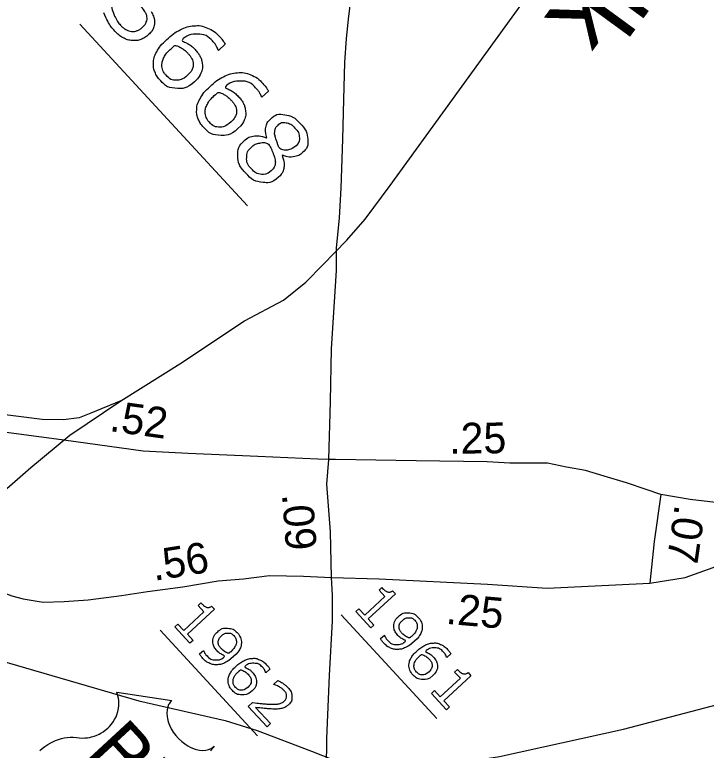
# Model space of a CAD drawing. Extents: x 1695041 to 1706254, y 786537 to 798223.
# Drawn here: x 1703301.4 to 1703431.2, y 796996.4 to 797134.4 of the extents above; entities that cross this region are included whole.
import ezdxf

# ---------------------------------------------------------------- set-up
doc = ezdxf.new("R2010")
doc.units = 0
for name, color, linetype in [('Default', 7, 'Continuous'), ('Old_Level_13', 7, 'Continuous'), ('Old_Level_29', 7, 'Continuous'), ('Old_Level_32', 7, 'Continuous'), ('Sheet Title CELL', 7, 'Continuous')]:
    doc.layers.add(name, color=color, linetype=linetype)

msp = doc.modelspace()

# ---------------------------------------------------------------- linework, layer by layer
at = {"layer": 'Default'}
for p, q in [((1703313.64, 797132.62), (1703345.11, 797098.53)), ((1703362.66, 797021.81), (1703380.63, 797002.34)), ((1703328.71, 797018.93), (1703346.97, 796999.14))]:
    msp.add_line(p, q, dxfattribs=at)
for points in [[(1703340.91, 797128.86), (1703339.66, 797127.7), (1703339.6, 797127.77)], [(1703349.03, 797120.06), (1703347.78, 797118.9), (1703347.72, 797118.97)], [(1703348.68, 797111.29), (1703348.72, 797111.33)], [(1703351.65, 797108.05), (1703351.61, 797108.01)], [(1703321.31, 797061.94), (1703315.69, 797059.63), (1703313.49, 797058.77), (1703310.57, 797058.37), (1703306.6, 797058.49), (1703295.15, 797059.93), (1703289.13, 797061.46), (1703284.84, 797063.34), (1703281.91, 797064.92), (1703278.04, 797067.22)], [(1703368.26, 797019.36), (1703365.44, 797022.42), (1703366.01, 797022.95), (1703367.1, 797021.78), (1703370.89, 797025.27), (1703369.8, 797026.45), (1703370.32, 797026.92)], [(1703372.32, 797026.34), (1703372.86, 797025.75), (1703367.77, 797021.05), (1703368.84, 797019.9), (1703368.26, 797019.36)], [(1703334.31, 797016.48), (1703331.49, 797019.54), (1703332.06, 797020.07), (1703333.15, 797018.9), (1703336.93, 797022.39), (1703335.85, 797023.57), (1703336.37, 797024.04)], [(1703338.37, 797023.46), (1703338.91, 797022.87), (1703333.82, 797018.17), (1703334.89, 797017.02), (1703334.31, 797016.48)], [(1703370.07, 797017.36), (1703370.8, 797018.03), (1703370.83, 797017.99)], [(1703291.97, 797015.19), (1703324.69, 797005.69), (1703340.9, 797002.01), (1703346.94, 797000.11), (1703357.14, 796996.22), (1703368.85, 796991.59), (1703392.4, 796995.22), (1703415.7, 797000.36), (1703437.39, 797006.05), (1703475.08, 797015.18), (1703510.21, 797012.82), (1703534.98, 797011.35), (1703569.35, 797009.42), (1703597.22, 797007.38), (1703614.23, 797006.26), (1703657.83, 797003.31), (1703684.12, 797001.47)], [(1703336.12, 797014.48), (1703336.85, 797015.15), (1703336.88, 797015.11)], [(1703383.24, 797014.5), (1703382.52, 797013.83), (1703382.48, 797013.87)], [(1703349.29, 797011.62), (1703348.57, 797010.95), (1703348.53, 797010.99)], [(1703382.43, 797004.01), (1703379.61, 797007.07), (1703380.19, 797007.6), (1703381.27, 797006.42), (1703385.06, 797009.92), (1703383.97, 797011.09), (1703384.49, 797011.57)], [(1703386.49, 797010.98), (1703387.04, 797010.39), (1703381.95, 797005.69), (1703383.01, 797004.54), (1703382.43, 797004.01)], [(1703350.03, 797008.72), (1703350, 797008.76), (1703350.79, 797009.49)], [(1703306.15, 796996.37), (1703306.57, 796996.73), (1703307.08, 796997.12), (1703307.66, 796997.5), (1703308.17, 796997.8), (1703308.56, 796998), (1703309.06, 796998.22), (1703309.63, 796998.43), (1703310.21, 796998.6), (1703310.71, 796998.72), (1703311.29, 796998.81), (1703311.8, 796998.85), (1703312.42, 796998.85), (1703313.02, 796998.81), (1703313.53, 796998.74), (1703314.19, 796998.71), (1703314.56, 796998.72), (1703315.05, 796998.76), (1703315.48, 796998.83), (1703315.84, 796998.92), (1703316.36, 796999.06), (1703316.73, 796999.19), (1703317.26, 796999.42), (1703317.61, 796999.62), (1703318.04, 796999.88), (1703318.42, 797000.16), (1703318.87, 797000.53), (1703319.21, 797000.87), (1703319.59, 797001.3), (1703319.91, 797001.75), (1703320.17, 797002.16), (1703320.43, 797002.68), (1703320.6, 797003.08), (1703320.78, 797003.68), (1703320.91, 797004.27), (1703320.96, 797004.81), (1703320.98, 797005.32), (1703320.94, 797005.76), (1703320.89, 797006.16), (1703320.8, 797006.64), (1703320.67, 797007.06), (1703320.57, 797007.32), (1703330.9, 797005.73), (1703330.66, 797005.48), (1703330.42, 797005.15), (1703330.31, 797004.97), (1703330.15, 797004.56), (1703330.02, 797004.01), (1703329.97, 797003.39), (1703330.01, 797002.76), (1703330.08, 797002.37), (1703330.23, 797001.76), (1703330.47, 797001.11), (1703330.8, 797000.46), (1703331.18, 796999.83), (1703331.65, 796999.2), (1703332.16, 796998.61), (1703332.78, 796998.04), (1703333.54, 796997.48), (1703333.91, 796997.24), (1703334.35, 796997), (1703334.79, 796996.8), (1703335.31, 796996.62), (1703335.76, 796996.5), (1703336.13, 796996.43), (1703336.73, 796996.39), (1703337.28, 796996.43), (1703337.56, 796996.48), (1703337.81, 796996.55), (1703338.29, 796996.76), (1703338.48, 796996.87), (1703338.84, 796997.15), (1703338.58, 796996.87), (1703338.43, 796996.68), (1703338.3, 796996.48), (1703338.19, 796996.24)], [(1703348.78, 797000.8), (1703345.25, 797004.63), (1703346.05, 797005.37)], [(1703346.63, 797004.45), (1703349.44, 797001.41), (1703348.78, 797000.8)]]:
    msp.add_lwpolyline(points, dxfattribs=at)
for points in [[(1703319.61, 797135.93), (1703319.76, 797135.04), (1703320.21, 797134.07), (1703320.66, 797133.1), (1703321.3, 797132.4), (1703321.68, 797131.99), (1703322.25, 797131.65), (1703322.81, 797131.31), (1703323.35, 797131.27), (1703323.91, 797131.24), (1703324.39, 797131.41), (1703324.88, 797131.58), (1703325.41, 797132.07), (1703325.93, 797132.56), (1703326.12, 797133.04), (1703326.31, 797133.52), (1703326.23, 797134), (1703326.16, 797134.48), (1703325.85, 797134.97), (1703325.54, 797135.45), (1703325.1, 797135.94)], [(1703327.67, 797133.04), (1703327.68, 797132.47), (1703327.44, 797131.87), (1703327.2, 797131.28), (1703326.53, 797130.66), (1703325.86, 797130.04), (1703325.09, 797129.77), (1703324.31, 797129.5), (1703323.49, 797129.56), (1703322.59, 797129.63), (1703321.76, 797130.09), (1703320.93, 797130.55), (1703320.2, 797131.34), (1703319.45, 797132.14), (1703318.92, 797133.1), (1703318.39, 797134.06), (1703318.16, 797134.78)], [(1703327.01, 797135.03), (1703327.24, 797134.66), (1703327.45, 797134.11), (1703327.66, 797133.55), (1703327.67, 797133.04)], [(1703335.18, 797121.83), (1703333.7, 797120.46), (1703331.87, 797120.57), (1703330.03, 797120.68), (1703328.73, 797122.1), (1703328.07, 797122.81), (1703327.75, 797123.6), (1703327.43, 797124.4), (1703327.45, 797125.25), (1703327.47, 797126.31), (1703328.09, 797127.44), (1703328.7, 797128.57), (1703329.96, 797129.73), (1703331.25, 797130.92), (1703332.5, 797131.56), (1703333.76, 797132.21), (1703335.09, 797132.32), (1703336.36, 797132.42), (1703337.61, 797131.9), (1703338.86, 797131.38), (1703339.98, 797130.17), (1703340.33, 797129.78), (1703340.54, 797129.49), (1703340.75, 797129.2), (1703340.91, 797128.86)], [(1703339.6, 797127.77), (1703339.53, 797128.04), (1703339.28, 797128.49), (1703339.03, 797128.94), (1703338.67, 797129.32), (1703337.38, 797130.72), (1703335.73, 797130.75), (1703334.09, 797130.77), (1703332.47, 797129.53), (1703333.31, 797129.29), (1703333.97, 797128.92), (1703334.63, 797128.55), (1703335.27, 797127.85), (1703335.84, 797127.23), (1703336.17, 797126.66), (1703336.49, 797126.08), (1703336.6, 797125.27), (1703336.73, 797124.33), (1703336.39, 797123.48), (1703336.05, 797122.63), (1703335.18, 797121.83)], [(1703333.91, 797123.1), (1703334.51, 797123.66), (1703334.74, 797124.2), (1703334.98, 797124.75), (1703334.89, 797125.43), (1703334.82, 797125.92), (1703334.55, 797126.34), (1703334.28, 797126.77), (1703333.91, 797127.16), (1703333.4, 797127.72), (1703332.83, 797128.07), (1703332.26, 797128.43), (1703331.53, 797128.68), (1703331.37, 797128.56), (1703331.23, 797128.44), (1703331.09, 797128.32), (1703330.89, 797128.14), (1703329.86, 797127.19), (1703329.46, 797126.43), (1703329.06, 797125.67), (1703329.06, 797124.98), (1703329.05, 797124.41), (1703329.24, 797123.94), (1703329.43, 797123.47), (1703329.81, 797123.06), (1703330.68, 797122.12), (1703331.75, 797122.11), (1703332.83, 797122.1), (1703333.91, 797123.1)], [(1703343.31, 797113.03), (1703341.83, 797111.66), (1703339.99, 797111.77), (1703338.16, 797111.88), (1703336.85, 797113.3), (1703336.19, 797114.02), (1703335.87, 797114.81), (1703335.55, 797115.6), (1703335.57, 797116.45), (1703335.59, 797117.51), (1703336.21, 797118.64), (1703336.82, 797119.77), (1703338.08, 797120.93), (1703339.37, 797122.12), (1703340.62, 797122.77), (1703341.88, 797123.41), (1703343.21, 797123.52), (1703344.48, 797123.63), (1703345.73, 797123.1), (1703346.98, 797122.58), (1703348.1, 797121.37), (1703348.45, 797120.99), (1703348.66, 797120.69), (1703348.87, 797120.4), (1703349.03, 797120.06)], [(1703347.72, 797118.97), (1703347.65, 797119.24), (1703347.4, 797119.69), (1703347.15, 797120.14), (1703346.79, 797120.53), (1703345.5, 797121.93), (1703343.85, 797121.95), (1703342.21, 797121.97), (1703340.59, 797120.73), (1703341.43, 797120.49), (1703342.09, 797120.12), (1703342.75, 797119.75), (1703343.39, 797119.05), (1703343.97, 797118.44), (1703344.29, 797117.86), (1703344.61, 797117.28), (1703344.72, 797116.47), (1703344.85, 797115.53), (1703344.51, 797114.68), (1703344.17, 797113.83), (1703343.31, 797113.03)], [(1703342.03, 797114.3), (1703342.63, 797114.86), (1703342.86, 797115.4), (1703343.1, 797115.95), (1703343.01, 797116.63), (1703342.94, 797117.12), (1703342.67, 797117.55), (1703342.4, 797117.97), (1703342.03, 797118.37), (1703341.52, 797118.92), (1703340.95, 797119.28), (1703340.39, 797119.63), (1703339.65, 797119.88), (1703339.49, 797119.76), (1703339.35, 797119.64), (1703339.22, 797119.53), (1703339.01, 797119.34), (1703337.98, 797118.39), (1703337.58, 797117.63), (1703337.18, 797116.87), (1703337.18, 797116.18), (1703337.17, 797115.62), (1703337.36, 797115.14), (1703337.55, 797114.67), (1703337.93, 797114.26), (1703338.8, 797113.32), (1703339.87, 797113.31), (1703340.95, 797113.3), (1703342.03, 797114.3)], [(1703348.72, 797111.33), (1703348.42, 797112.49), (1703348.57, 797113.33), (1703348.72, 797114.16), (1703349.46, 797114.85), (1703350.55, 797115.86), (1703352.12, 797115.63), (1703353.68, 797115.4), (1703354.96, 797114.02), (1703356.3, 797112.56), (1703356.41, 797111.05), (1703356.51, 797109.54), (1703355.43, 797108.54), (1703354.77, 797107.94), (1703353.76, 797107.76), (1703352.74, 797107.59), (1703351.65, 797108.05)], [(1703354.23, 797109.82), (1703354.93, 797110.46), (1703354.85, 797111.38), (1703354.77, 797112.3), (1703353.99, 797113.14), (1703353.23, 797113.96), (1703352.36, 797114.13), (1703351.48, 797114.29), (1703350.82, 797113.68), (1703350.35, 797113.24), (1703350.25, 797112.66), (1703350.15, 797112.08), (1703350.38, 797111.3), (1703350.48, 797110.95), (1703350.71, 797110.32), (1703350.94, 797109.69), (1703351.22, 797109.15), (1703352.24, 797108.9), (1703352.94, 797109.08), (1703353.63, 797109.26), (1703354.23, 797109.82)], [(1703350.92, 797103.9), (1703349.66, 797102.73), (1703347.92, 797102.95), (1703346.18, 797103.16), (1703344.81, 797104.64), (1703343.35, 797106.22), (1703343.3, 797107.91), (1703343.25, 797109.6), (1703344.52, 797110.77), (1703345.33, 797111.52), (1703346.42, 797111.65), (1703347.51, 797111.79), (1703348.68, 797111.29)], [(1703349.56, 797105.12), (1703350.16, 797105.68), (1703350.28, 797106.27), (1703350.4, 797106.87), (1703350.05, 797107.98), (1703349.91, 797108.42), (1703349.7, 797108.9), (1703349.48, 797109.38), (1703349.14, 797110.19), (1703348.28, 797110.48), (1703347.41, 797110.33), (1703346.54, 797110.18), (1703345.84, 797109.54), (1703344.97, 797108.73), (1703344.95, 797107.59), (1703344.94, 797106.46), (1703345.8, 797105.53), (1703346.68, 797104.57), (1703347.69, 797104.45), (1703348.71, 797104.33), (1703349.56, 797105.12)], [(1703351.61, 797108.01), (1703352.06, 797106.74), (1703351.94, 797105.73), (1703351.81, 797104.71), (1703350.92, 797103.9)], [(1703370.32, 797026.92), (1703370.54, 797026.69), (1703370.83, 797026.45), (1703371.12, 797026.21), (1703371.33, 797026.14), (1703371.58, 797026.06), (1703371.82, 797026.09), (1703372.06, 797026.12), (1703372.32, 797026.34)], [(1703336.37, 797024.04), (1703336.59, 797023.8), (1703336.88, 797023.57), (1703337.17, 797023.33), (1703337.37, 797023.26), (1703337.63, 797023.17), (1703337.87, 797023.21), (1703338.11, 797023.24), (1703338.37, 797023.46)], [(1703370.83, 797017.99), (1703370.87, 797017.83), (1703371.01, 797017.58), (1703371.14, 797017.33), (1703371.37, 797017.09), (1703372.14, 797016.25), (1703373.08, 797016.24), (1703374.03, 797016.23), (1703374.98, 797016.97), (1703374.44, 797017.12), (1703374.06, 797017.35), (1703373.69, 797017.58), (1703373.35, 797017.94), (1703373.02, 797018.29), (1703372.83, 797018.64), (1703372.64, 797018.98), (1703372.58, 797019.45), (1703372.5, 797020), (1703372.7, 797020.49), (1703372.9, 797020.99), (1703373.4, 797021.45), (1703374.27, 797022.25), (1703375.33, 797022.18), (1703376.4, 797022.12), (1703377.16, 797021.3), (1703377.54, 797020.89), (1703377.73, 797020.42), (1703377.93, 797019.95), (1703377.91, 797019.46), (1703377.9, 797018.84), (1703377.56, 797018.21), (1703377.23, 797017.58), (1703376.44, 797016.86)], [(1703375.9, 797017.78), (1703376.48, 797018.32), (1703376.73, 797018.77), (1703376.97, 797019.22), (1703376.98, 797019.62), (1703376.98, 797019.95), (1703376.87, 797020.22), (1703376.75, 797020.5), (1703376.53, 797020.74), (1703376.03, 797021.28), (1703375.4, 797021.28), (1703374.76, 797021.28), (1703374.14, 797020.71), (1703373.78, 797020.38), (1703373.65, 797020.07), (1703373.52, 797019.75), (1703373.57, 797019.36), (1703373.61, 797019.08), (1703373.76, 797018.83), (1703373.91, 797018.59), (1703374.14, 797018.34), (1703374.41, 797018.05), (1703374.77, 797017.82), (1703375.13, 797017.59), (1703375.53, 797017.46), (1703375.61, 797017.53), (1703375.69, 797017.6), (1703375.77, 797017.67), (1703375.9, 797017.78)], [(1703336.88, 797015.11), (1703336.92, 797014.95), (1703337.06, 797014.7), (1703337.19, 797014.45), (1703337.42, 797014.21), (1703338.19, 797013.37), (1703339.13, 797013.36), (1703340.07, 797013.35), (1703341.03, 797014.09), (1703340.49, 797014.24), (1703340.11, 797014.47), (1703339.73, 797014.7), (1703339.4, 797015.06), (1703339.07, 797015.41), (1703338.88, 797015.76), (1703338.69, 797016.1), (1703338.62, 797016.57), (1703338.55, 797017.12), (1703338.75, 797017.61), (1703338.95, 797018.11), (1703339.45, 797018.57), (1703340.32, 797019.37), (1703341.38, 797019.3), (1703342.45, 797019.24), (1703343.21, 797018.42), (1703343.59, 797018.01), (1703343.78, 797017.54), (1703343.98, 797017.07), (1703343.96, 797016.58), (1703343.95, 797015.96), (1703343.61, 797015.33), (1703343.28, 797014.7), (1703342.49, 797013.97)], [(1703341.95, 797014.9), (1703342.53, 797015.44), (1703342.78, 797015.89), (1703343.02, 797016.34), (1703343.02, 797016.74), (1703343.03, 797017.07), (1703342.92, 797017.34), (1703342.8, 797017.62), (1703342.58, 797017.86), (1703342.08, 797018.4), (1703341.44, 797018.4), (1703340.81, 797018.4), (1703340.19, 797017.83), (1703339.83, 797017.5), (1703339.7, 797017.19), (1703339.57, 797016.87), (1703339.62, 797016.47), (1703339.66, 797016.2), (1703339.81, 797015.95), (1703339.96, 797015.71), (1703340.19, 797015.46), (1703340.46, 797015.17), (1703340.82, 797014.94), (1703341.18, 797014.71), (1703341.57, 797014.58), (1703341.66, 797014.65), (1703341.74, 797014.72), (1703341.82, 797014.79), (1703341.95, 797014.9)], [(1703376.44, 797016.86), (1703375.7, 797016.17), (1703374.94, 797015.78), (1703374.18, 797015.39), (1703373.44, 797015.34), (1703372.69, 797015.29), (1703371.97, 797015.59), (1703371.26, 797015.89), (1703370.61, 797016.6), (1703370.43, 797016.79), (1703370.29, 797016.99), (1703370.15, 797017.18), (1703370.07, 797017.36)], [(1703379.91, 797010.41), (1703379.05, 797009.62), (1703377.99, 797009.68), (1703376.92, 797009.74), (1703376.16, 797010.57), (1703375.77, 797010.98), (1703375.59, 797011.45), (1703375.4, 797011.91), (1703375.41, 797012.4), (1703375.43, 797013.02), (1703375.78, 797013.68), (1703376.14, 797014.33), (1703376.87, 797015.01), (1703377.63, 797015.7), (1703378.35, 797016.08), (1703379.08, 797016.45), (1703379.86, 797016.51), (1703380.6, 797016.58), (1703381.33, 797016.27), (1703382.05, 797015.97), (1703382.7, 797015.26), (1703382.91, 797015.04), (1703383.03, 797014.87), (1703383.15, 797014.7), (1703383.24, 797014.5)], [(1703342.49, 797013.97), (1703341.75, 797013.29), (1703340.99, 797012.9), (1703340.23, 797012.51), (1703339.49, 797012.46), (1703338.74, 797012.41), (1703338.02, 797012.71), (1703337.31, 797013.01), (1703336.66, 797013.72), (1703336.48, 797013.91), (1703336.34, 797014.11), (1703336.2, 797014.3), (1703336.12, 797014.48)], [(1703379.17, 797011.15), (1703379.52, 797011.48), (1703379.66, 797011.79), (1703379.79, 797012.11), (1703379.74, 797012.51), (1703379.7, 797012.79), (1703379.55, 797013.04), (1703379.39, 797013.29), (1703379.17, 797013.52), (1703378.88, 797013.84), (1703378.55, 797014.05), (1703378.22, 797014.25), (1703377.79, 797014.4), (1703377.7, 797014.33), (1703377.62, 797014.26), (1703377.53, 797014.19), (1703377.42, 797014.08), (1703376.82, 797013.53), (1703376.59, 797013.09), (1703376.35, 797012.64), (1703376.35, 797012.24), (1703376.35, 797011.92), (1703376.45, 797011.64), (1703376.56, 797011.37), (1703376.78, 797011.13), (1703377.29, 797010.58), (1703377.92, 797010.57), (1703378.54, 797010.57), (1703379.17, 797011.15)], [(1703382.48, 797013.87), (1703382.44, 797014.03), (1703382.29, 797014.29), (1703382.15, 797014.55), (1703381.94, 797014.77), (1703381.19, 797015.59), (1703380.23, 797015.6), (1703379.28, 797015.62), (1703378.33, 797014.89), (1703378.82, 797014.75), (1703379.21, 797014.54), (1703379.59, 797014.32), (1703379.97, 797013.92), (1703380.3, 797013.56), (1703380.49, 797013.22), (1703380.67, 797012.89), (1703380.74, 797012.41), (1703380.81, 797011.86), (1703380.62, 797011.37), (1703380.42, 797010.88), (1703379.91, 797010.41)], [(1703345.96, 797007.53), (1703345.1, 797006.74), (1703344.03, 797006.8), (1703342.97, 797006.86), (1703342.21, 797007.69), (1703341.82, 797008.1), (1703341.64, 797008.56), (1703341.45, 797009.03), (1703341.46, 797009.52), (1703341.48, 797010.14), (1703341.83, 797010.79), (1703342.19, 797011.45), (1703342.92, 797012.13), (1703343.67, 797012.82), (1703344.4, 797013.2), (1703345.13, 797013.57), (1703345.91, 797013.63), (1703346.65, 797013.7), (1703347.38, 797013.39), (1703348.1, 797013.09), (1703348.75, 797012.38), (1703348.96, 797012.16), (1703349.08, 797011.99), (1703349.2, 797011.82), (1703349.29, 797011.62)], [(1703348.53, 797010.99), (1703348.49, 797011.14), (1703348.34, 797011.41), (1703348.2, 797011.67), (1703347.99, 797011.89), (1703347.24, 797012.71), (1703346.28, 797012.72), (1703345.32, 797012.74), (1703344.38, 797012.01), (1703344.87, 797011.87), (1703345.26, 797011.66), (1703345.64, 797011.44), (1703346.02, 797011.04), (1703346.35, 797010.68), (1703346.53, 797010.34), (1703346.72, 797010), (1703346.79, 797009.53), (1703346.86, 797008.98), (1703346.67, 797008.49), (1703346.47, 797008), (1703345.96, 797007.53)], [(1703384.49, 797011.57), (1703384.71, 797011.33), (1703385, 797011.09), (1703385.3, 797010.86), (1703385.5, 797010.79), (1703385.76, 797010.7), (1703386, 797010.73), (1703386.23, 797010.77), (1703386.49, 797010.98)], [(1703345.22, 797008.27), (1703345.57, 797008.59), (1703345.71, 797008.91), (1703345.84, 797009.23), (1703345.79, 797009.63), (1703345.75, 797009.91), (1703345.59, 797010.16), (1703345.44, 797010.41), (1703345.22, 797010.64), (1703344.93, 797010.96), (1703344.6, 797011.16), (1703344.26, 797011.37), (1703343.84, 797011.52), (1703343.75, 797011.45), (1703343.66, 797011.38), (1703343.58, 797011.31), (1703343.47, 797011.2), (1703342.87, 797010.65), (1703342.63, 797010.21), (1703342.4, 797009.76), (1703342.4, 797009.36), (1703342.39, 797009.04), (1703342.5, 797008.76), (1703342.61, 797008.49), (1703342.83, 797008.25), (1703343.34, 797007.7), (1703343.97, 797007.69), (1703344.59, 797007.69), (1703345.22, 797008.27)], [(1703350.79, 797009.49), (1703351.17, 797009.35), (1703351.7, 797009), (1703352.22, 797008.65), (1703352.61, 797008.23), (1703353.42, 797007.36), (1703353.45, 797006.48), (1703353.49, 797005.6), (1703352.77, 797004.93), (1703352.45, 797004.64), (1703352.1, 797004.46), (1703351.74, 797004.29), (1703351.35, 797004.21), (1703350.98, 797004.15), (1703350.56, 797004.13), (1703350.15, 797004.12), (1703349.61, 797004.15), (1703348.84, 797004.19), (1703348.07, 797004.28), (1703347.29, 797004.37), (1703346.63, 797004.45)], [(1703346.05, 797005.37), (1703346.76, 797005.28), (1703347.47, 797005.2), (1703348.18, 797005.11), (1703348.84, 797005.08), (1703350.22, 797005), (1703350.88, 797005.11), (1703351.55, 797005.23), (1703352.03, 797005.67), (1703352.47, 797006.08), (1703352.45, 797006.6), (1703352.43, 797007.12), (1703351.94, 797007.64), (1703351.62, 797007.98), (1703351.13, 797008.28), (1703350.64, 797008.57), (1703350.03, 797008.72)]]:
    msp.add_open_spline(points, degree=3, dxfattribs=at)
at = {"layer": 'Old_Level_13'}
for points in [[(1703321.31, 797061.94), (1703332.38, 797068.88), (1703344.54, 797076.96), (1703351.89, 797080.84), (1703356.03, 797084.25), (1703359.25, 797087.45), (1703363.77, 797092.08), (1703367.17, 797096.04), (1703371.9, 797102.36), (1703383.58, 797118.52), (1703398.38, 797139.03), (1703411.79, 797157.78), (1703419.75, 797168.69), (1703426.47, 797178.18), (1703431.77, 797184.16), (1703436.92, 797189.22), (1703444.25, 797195.29), (1703454.5, 797203.41), (1703467.2, 797213.48), (1703479.07, 797223.61)], [(1703281.63, 797024.14), (1703285.78, 797029.59), (1703290.2, 797035.41), (1703295.86, 797041.99), (1703304.43, 797049.44), (1703311.79, 797055.55), (1703321.31, 797061.94)]]:
    msp.add_lwpolyline(points, dxfattribs=at)
at = {"layer": 'Old_Level_29'}
for points in [[(1703361.81, 797090.58), (1703362.39, 797096.27), (1703362.68, 797101.88), (1703362.97, 797111.06), (1703363.18, 797118.52), (1703363.38, 797125.42), (1703363.68, 797129.96), (1703364.15, 797134.1), (1703364.73, 797139.07)], [(1703360.37, 797050.96), (1703360.71, 797061.82), (1703360.89, 797071.7), (1703361.83, 797086.44), (1703361.81, 797090.58)], [(1703360.87, 797028.8), (1703360.66, 797037.38), (1703360.01, 797046.36), (1703360.37, 797050.96)], [(1703358.82, 796957.22), (1703359.08, 796959.98), (1703359.07, 796962.7), (1703359.64, 796975.95), (1703359.85, 796987.16), (1703360.02, 796998.63), (1703360.5, 797010.45), (1703361.06, 797020.72), (1703361.07, 797025.52), (1703360.87, 797028.8)]]:
    msp.add_lwpolyline(points, dxfattribs=at)
at = {"layer": 'Old_Level_32'}
for points in [[(1703360.37, 797050.96), (1703358.3, 797051.03), (1703347.02, 797051.54), (1703333.96, 797052.06), (1703325.52, 797052.49), (1703310.67, 797054.58), (1703285.33, 797057.94), (1703280.89, 797058.46), (1703271.59, 797059.5), (1703254.83, 797061.07), (1703250.08, 797061.63), (1703248.08, 797062.01), (1703241.69, 797063.98), (1703235.91, 797066.04)], [(1703235.91, 797066.04), (1703241.51, 797059.46), (1703248.07, 797054.12), (1703250.98, 797051.99), (1703252.65, 797050.95), (1703261.55, 797045.89), (1703274.5, 797038.47), (1703288.97, 797030.5), (1703291.93, 797029.05), (1703295.11, 797027.48), (1703300.86, 797025.4), (1703302.98, 797024.82), (1703306.79, 797024.22), (1703310.71, 797024.3), (1703315.18, 797024.6), (1703321.45, 797025.43), (1703326.34, 797026.21), (1703332.98, 797027.1), (1703339.58, 797028.17), (1703344.36, 797028.55), (1703349.26, 797029.17), (1703355.63, 797029.05), (1703360.87, 797028.8)], [(1703422.68, 797044.39), (1703419.95, 797045.36), (1703416.26, 797046.58), (1703412.07, 797047.82), (1703408.53, 797048.89), (1703404.98, 797049.54), (1703401.38, 797050.25), (1703394.35, 797050.25), (1703390.06, 797050.53), (1703376.74, 797050.71), (1703361.61, 797050.93), (1703360.37, 797050.96)], [(1703452.49, 797048.19), (1703447.3, 797045.95), (1703442.26, 797044.17), (1703437.25, 797043.23), (1703432.91, 797042.91), (1703428.18, 797043.46), (1703422.68, 797044.39)], [(1703420.61, 797027.76), (1703427.23, 797028.83), (1703432.5, 797030.72), (1703437.57, 797033.01), (1703445.26, 797037.42), (1703455.9, 797045.61)], [(1703422.68, 797044.39), (1703421.41, 797035.57), (1703420.61, 797027.76)], [(1703360.87, 797028.8), (1703369.81, 797028.6), (1703390.12, 797027.54), (1703401.36, 797026.81), (1703420.61, 797027.76)]]:
    msp.add_lwpolyline(points, dxfattribs=at)

# ---------------------------------------------------------------- texts
at = {"layer": 'Default'}
for s, height, rotation, p in [('Norfolk', 14.412, 233.877, (1703436.71, 797183.16)), ('.52', 5.775, 351.9869, (1703319.05, 797056.32)), ('.25', 5.775, 0.6106, (1703382.97, 797052.03)), ('.09', 5.775, 274.1931, (1703351.58, 797044.43)), ('.07', 5.775, 261.7858, (1703425.34, 797042.63)), ('.56', 5.775, 9.1145, (1703327.57, 797028.18)), ('.25', 5.775, 354.993, (1703382.22, 797020.15)), ('BUS', 10.569, 312.7091, (1703314.56, 796995.77))]:
    msp.add_text(s, height=height, rotation=rotation, dxfattribs=at).set_placement(p)
at = {"layer": 'Sheet Title CELL'}
msp.add_text('See Sheet 1-A For Index of Sheets', height=22.5, rotation=312.7091, dxfattribs=at).set_placement((1703379.74, 797426.2))

doc.saveas('drawing.dxf')
